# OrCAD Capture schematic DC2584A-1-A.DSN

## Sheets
1 Active Bridge: size Custom
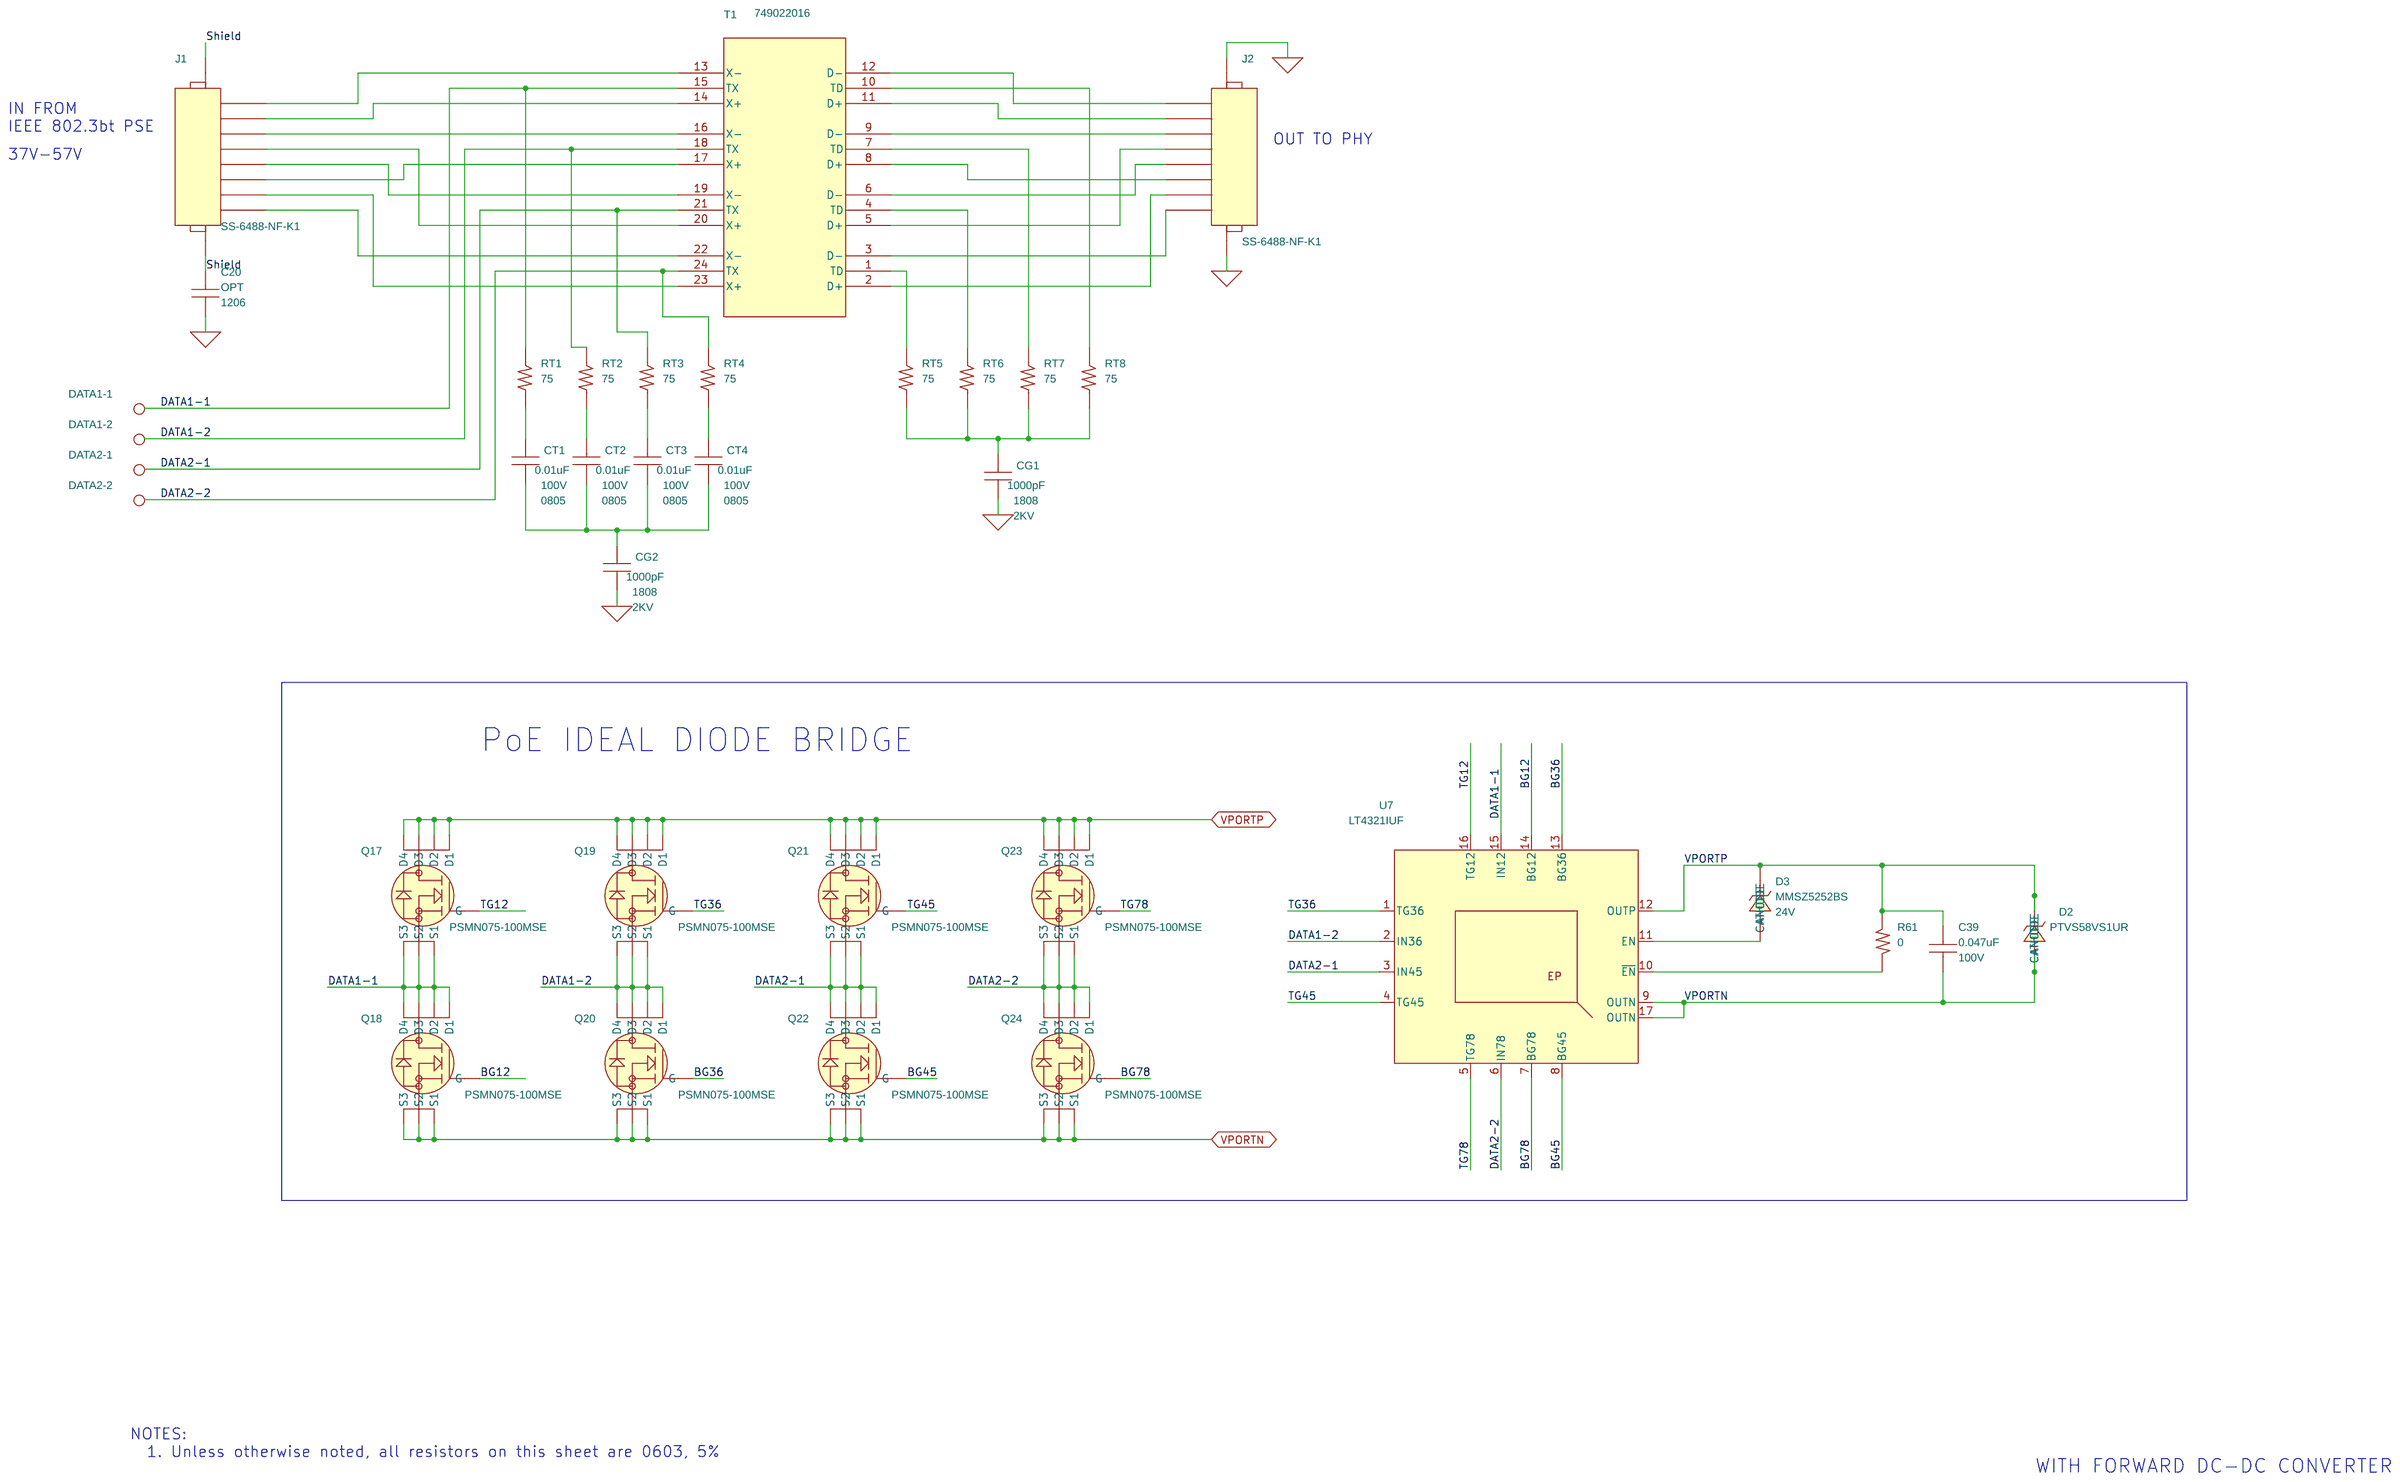
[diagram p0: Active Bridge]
2 Gate Driver Clamps: size Custom; title: IEEE 802.3bt POWERED DEVICE INTERFACE; rev: 1; company: TM
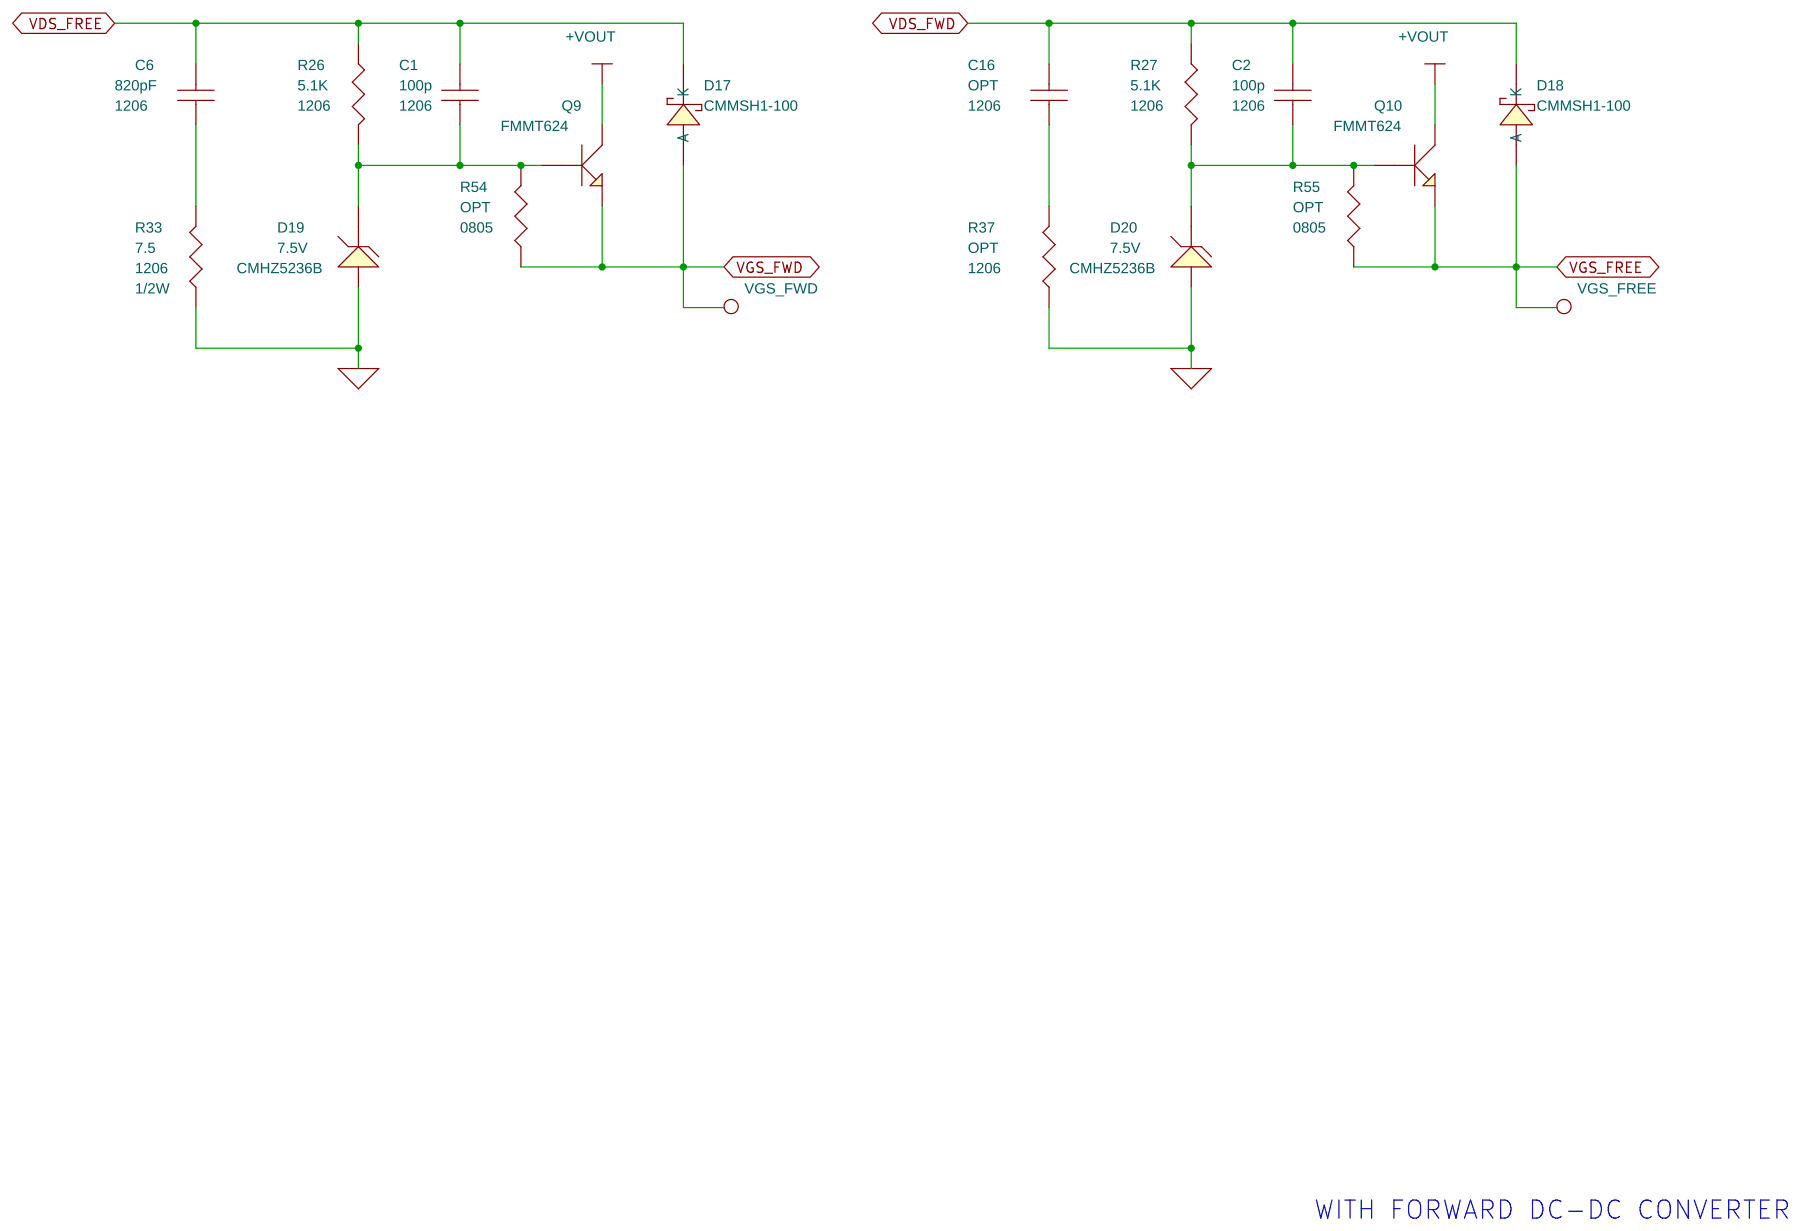
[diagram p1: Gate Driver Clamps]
3 PD + Power Supply: size Custom
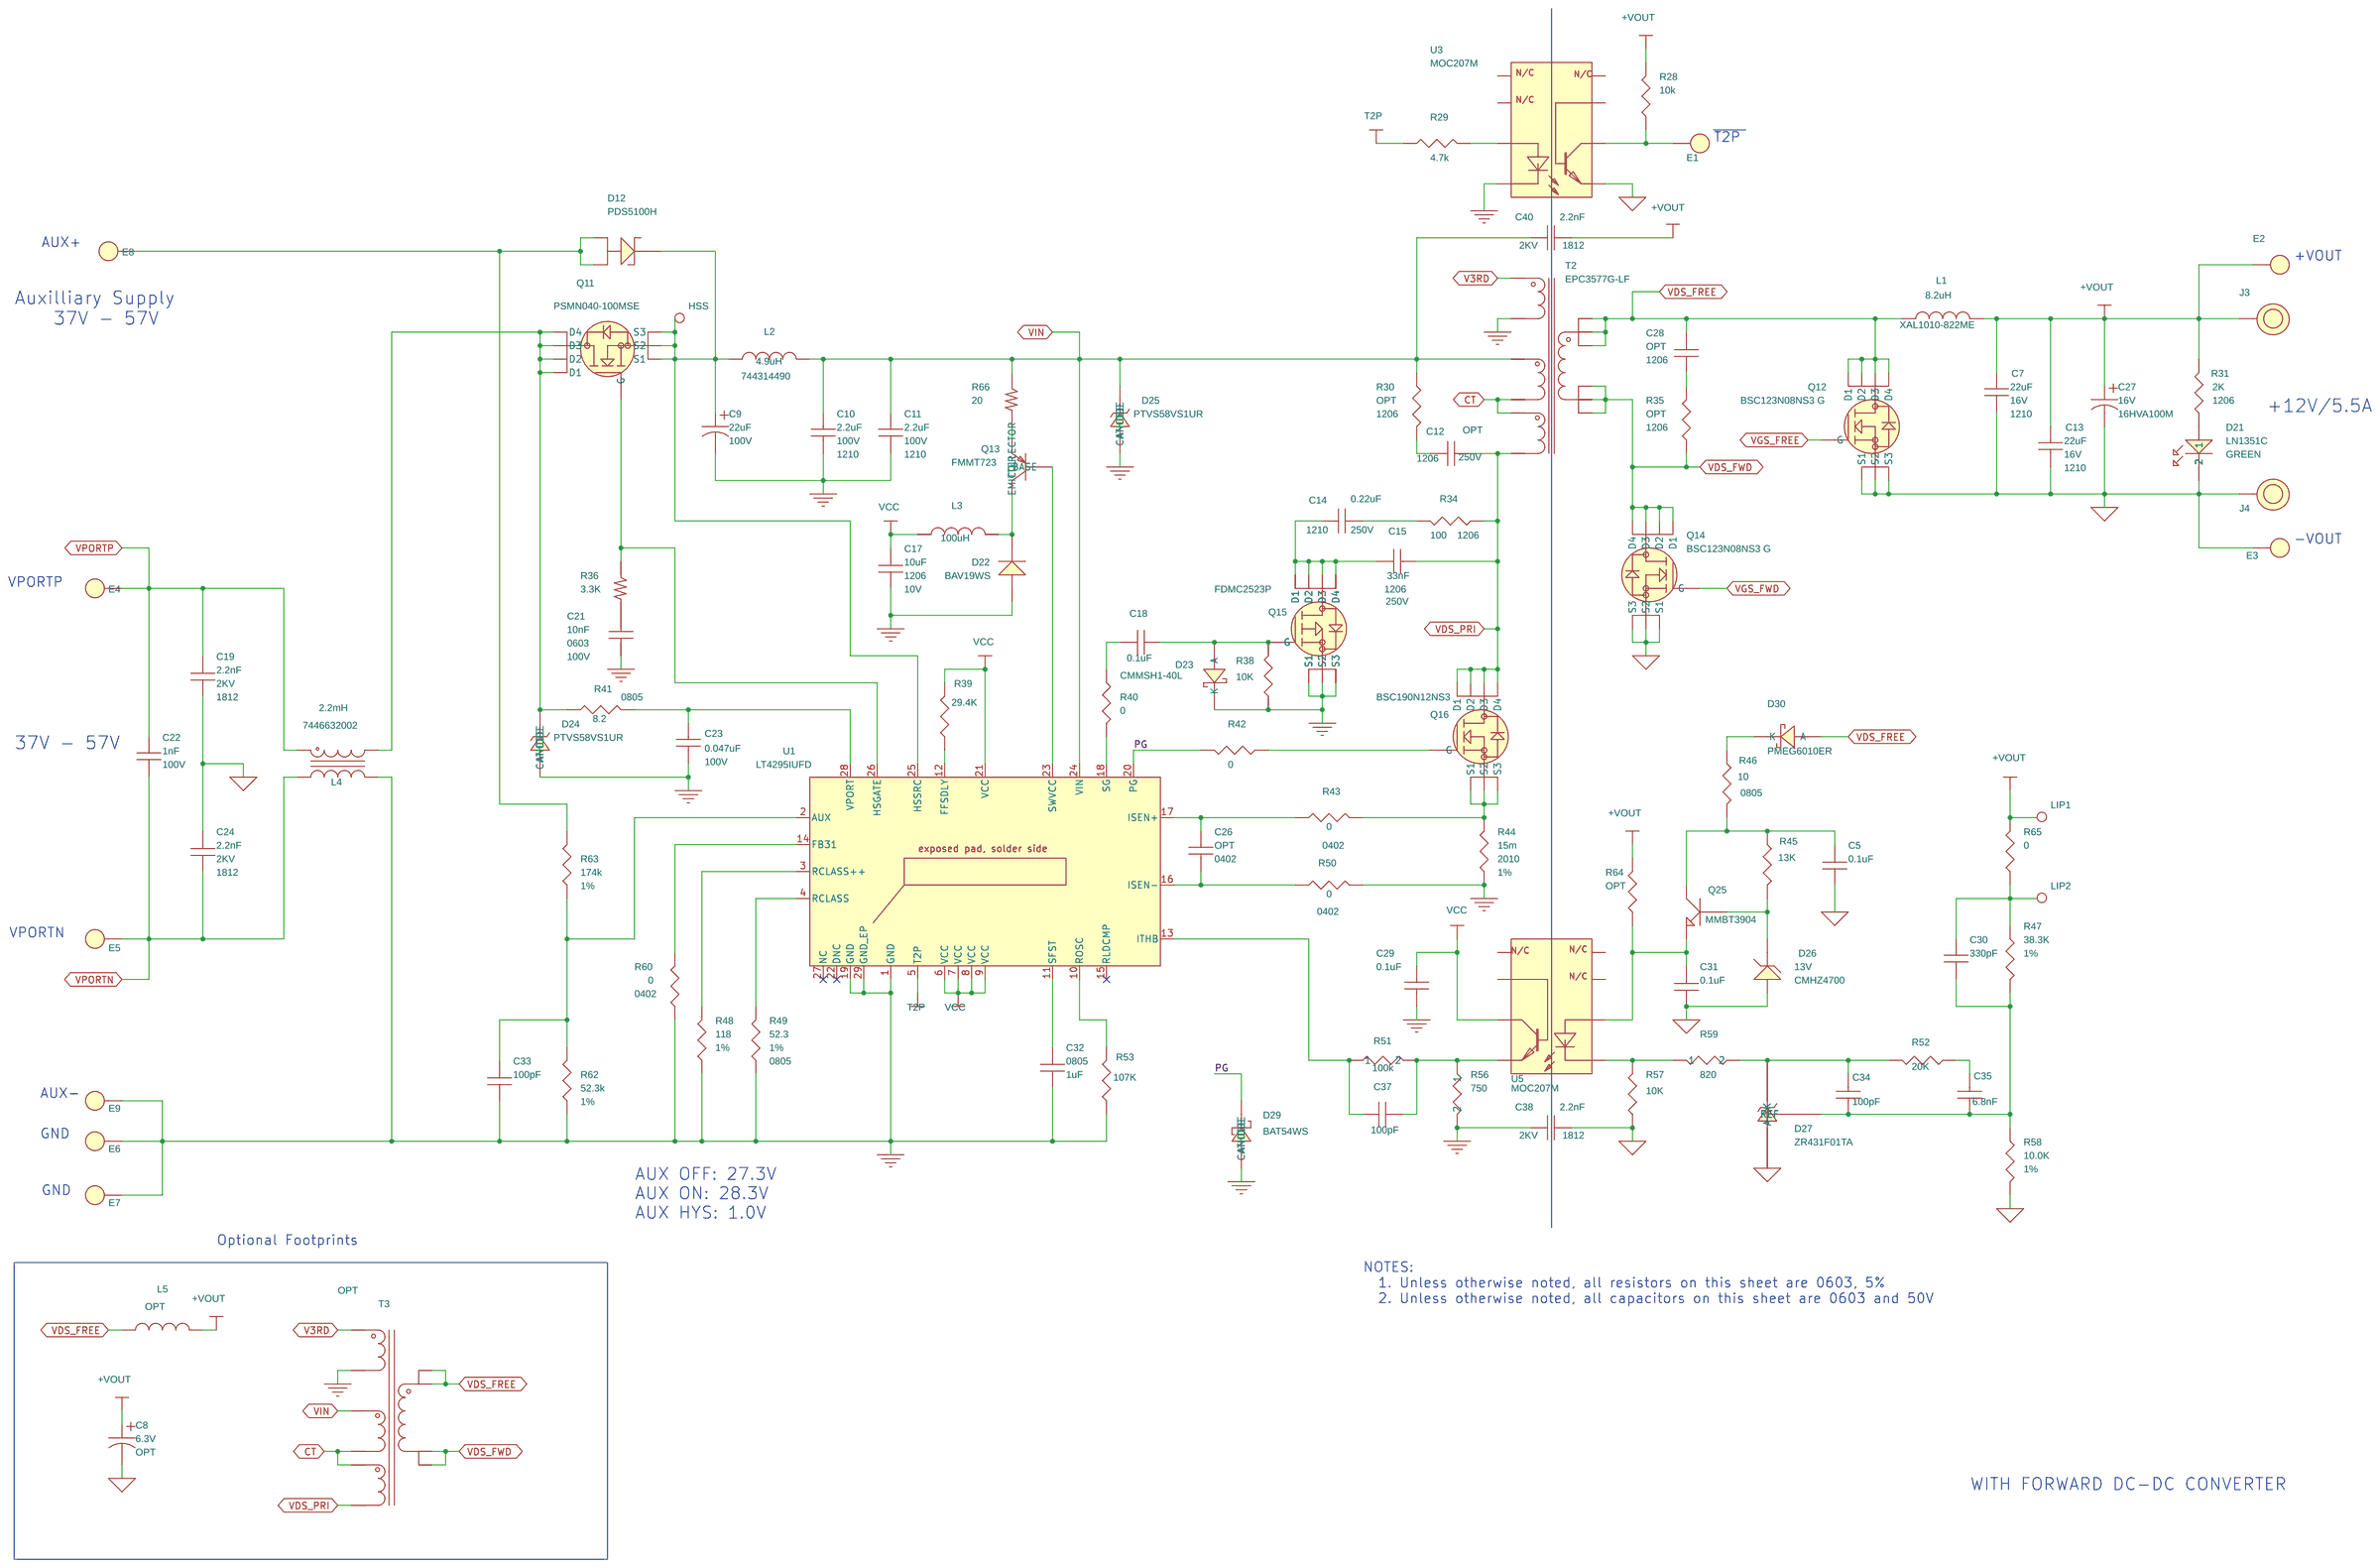
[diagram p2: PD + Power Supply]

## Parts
sheet Active Bridge
C20  OPT  [1206]
C39  0.047uF  [0603]
CG1  1000pF  [1808]
CG2  1000pF  [1808]
CT1  0.01uF  [0805]
CT2  0.01uF  [0805]
CT3  0.01uF  [0805]
CT4  0.01uF  [0805]
D2  PTVS58VS1UR  [SOD123]
D3  MMSZ5252BS  [SOD323]
DATA1-1  E-SMT-060  [SMTP]
DATA1-2  E-SMT-060  [SMTP]
DATA2-1  E-SMT-060  [SMTP]
DATA2-2  E-SMT-060  [SMTP]
J1  SS-6488-NF-K1  [CON-SS7188]
J2  SS-6488-NF-K1  [CON-SS7188]
Q17  PSMN075-100MSE  [POWERPAK1212]
Q18  PSMN075-100MSE  [POWERPAK1212]
Q19  PSMN075-100MSE  [POWERPAK1212]
Q20  PSMN075-100MSE  [POWERPAK1212]
Q21  PSMN075-100MSE  [POWERPAK1212]
Q22  PSMN075-100MSE  [POWERPAK1212]
Q23  PSMN075-100MSE  [POWERPAK1212]
Q24  PSMN075-100MSE  [POWERPAK1212]
R61  0  [0603]
RT1  75  [0603]
RT2  75  [0603]
RT3  75  [0603]
RT4  75  [0603]
RT5  75  [0603]
RT6  75  [0603]
RT7  75  [0603]
RT8  75  [0603]
T1  749022016  [749022016]
U7  LT4321IUF  [QFN16UF-4X4]
sheet Gate Driver Clamps
C1  100p  [1206]
C2  100p  [1206]
C6  820pF  [1206]
C16  OPT  [1206]
D17  CMMSH1-100  [SOD123F]
D18  CMMSH1-100  [SOD123F]
D19  CMHZ5236B  [SOD123]
D20  CMHZ5236B  [SOD123]
Q9  FMMT624  [SOT23]
Q10  FMMT624  [SOT23]
R26  5.1K  [1206]
R27  5.1K  [1206]
R33  7.5  [1206]
R37  OPT  [1206]
R54  OPT  [0805]
R55  OPT  [0805]
VGS_FREE  E-SMT-060  [SMTP]
VGS_FWD  E-SMT-060  [SMTP]
sheet PD + Power Supply
C5  0.1uF  [0603]
C7  22uF  [1210]
C8  OPT  [C-SANYO-CV-FS-6.3X6.0]
C9  22uF  [C-SANYO-CE-BS-8X10.2]
C10  2.2uF  [1210]
C11  2.2uF  [1210]
C12  OPT  [1206]
C13  22uF  [1210]
C14  0.22uF  [1206]
C15  33nF  [1206]
C17  10uF  [1206]
C18  0.1uF  [0603]
C19  2.2nF  [1812]
C21  10nF  [0603]
C22  1nF  [0603]
C23  0.047uF  [0603]
C24  2.2nF  [1812]
C26  OPT  [0402]
C27  100uF  [C-SANYO-HVH-8x10.5]
C28  OPT  [1206]
C29  0.1uF  [0603]
C30  330pF  [0603]
C31  0.1uF  [0603]
C32  1uF  [0805]
C33  100pF  [0603]
C34  100pF  [0603]
C35  6.8nF  [0603]
C37  100pF  [0603]
C38  2.2nF  [1812]
C40  2.2nF  [1812]
D12  PDS5100H  [POWER-DI-5]
D21  LN1351C  [LED-LN1351C-GREEN]
D22  BAV19WS  [SOD323]
D23  CMMSH1-40L  [SOD123F]
D24  PTVS58VS1UR  [SOD123]
D25  PTVS58VS1UR  [SOD123]
D26  CMHZ4700  [SOD123]
D27  ZR431F01TA  [SOT23]
D29  BAT54WS  [SOD323]
D30  PMEG6010ER  [SOD123F]
E1  PAD150-094  [PAD150-094]
E2  PAD150-094  [PAD150-094]
E3  PAD150-094  [PAD150-094]
E4  PAD150-094  [PAD150-094]
E5  PAD150-094  [PAD150-094]
E6  PAD150-094  [PAD150-094]
E7  PAD150-094  [PAD150-094]
E8  PAD150-094  [PAD150-094]
E9  PAD150-094  [PAD150-094]
HSS  E-SMT-060  [SMTP]
J3  575-4  [KEY-575-4]
J4  575-4  [KEY-575-4]
L1  8.2uH  [IND-COILCRAFT-XAL1010-102]
L2  4.9uH  [IND-744314490]
L3  100uH  [IND-DT1608C]
L4  2.2mH  [IND-7446632002]
L5  OPT  [IND-HC1]
LIP1  E-SMT-060  [SMTP]
LIP2  E-SMT-060  [SMTP]
Q11  PSMN040-100MSE  [POWER33]
Q12  BSC123N08NS3 G  [SO8-POWERPAK-BIG-NS]
Q13  FMMT723  [SOT23]
Q14  BSC123N08NS3 G  [SO8-POWERPAK-BIG-NS]
Q15  FDMC2523P  [POWER33]
Q16  BSC190N12NS3  [SO8-POWERPAK-BIG-NS]
Q25  MMBT3904  [SOT23]
R28  10k  [0603]
R29  4.7k  [0603]
R30  OPT  [1206]
R31  2K  [1206]
R34  100  [1206]
R35  OPT  [1206]
R36  3.3K  [0603]
R38  10K  [0603]
R39  29.4K  [0603]
R40  0  [0603]
R41  8.2  [0805]
R42  0  [0603]
R43  0  [0402]
R44  15m  [2010]
R45  13K  [0603]
R46  10  [0805]
R47  38.3K  [0603]
R48  118  [0603]
R49  52.3  [0805]
R50  0  [0402]
R51  100k  [0603]
R52  20K  [0603]
R53  107K  [0603]
R56  750  [0603]
R57  10K  [0603]
R58  10.0K  [0603]
R59  820  [0603]
R60  0  [0402]
R62  52.3k  [0603]
R63  174k  [0603]
R64  OPT  [0603]
R65  0  [0603]
R66  20  [0805]
T2  EPC3577G-LF  [TRANS-PB2134]
T3  OPT  [TRANS-PH08XXCNL]
U1  LT4295IUFD  [QFN28UFD-4X5]
U3  MOC207M  [SO8NB]
U5  MOC207M  [SO8NB]

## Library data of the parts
C12 C20 = CAP-NP: 1st Part: CAP; 2nd Part Type: CER; 3rd Tempco: X7R; 5th Voltage: 250V; 6th Tolerance: 10%; 8th Mfr: TBD; 9th Part Number: TBD
C39 = CAP-NP: 1st Part: CAP; 2nd Part Type: Cer; 3rd Tempco: X7R; 5th Voltage: 100V; 6th Tolerance: 20%; 8th Mfr: TBD; Voltage Rating: 100V
CG1 CG2 = CAP-NP: 1st Part: CAP; 2nd Part Type: CER; 3rd Tempco: X7R; 5th Voltage: 2KV; 6th Tolerance: ??%; 8th Mfr: TBD; 9th Part Number: TBD; Voltage Rating: 2KV
CT1-CT4 = CAP-NP: 1st Part: CAP; 2nd Part Type: CER; 3rd Tempco: X7R; 5th Voltage: 100V; 6th Tolerance: 20%; 8th Mfr: TBD; 9th Part Number: TBD; Voltage Rating: 100V
D2 = DIODE_ZENER_0: 1st Part: DIODE; 2nd Part Type: TVS; 5th Voltage: 60; 8th Mfr: NXP
D3 = DIODE_ZENER_0: 1st Part: DIODE; 2nd Part Type: Zener; 5th Voltage: 24V; 8th Mfr: Diodes Inc
DATA1-1 DATA1-2 DATA2-1 DATA2-2 HSS LIP1 LIP2 VGS_FREE VGS_FWD = E-SMT-060: 1st Part: CONN; 2nd Part Type: TP
J1 J2 = 8_HEADER_1: 1st Part: CONN; 2nd Part Type: RJ-45; 8th Mfr: STEWART CONNECTOR
Q17-Q24 = MOSFET_N-DIODE-A-SO8: 1st Part: MOSFET; 2nd Part Type: N-CH; 5th Voltage: 100; 7th Size: LFPAK33; 8th Mfr: NXP
R61 = R: 1st Part: Res; 2nd Part Type: Chip; 6th Tolerance: 5%; 8th Mfr: TBD; Tolerance: 5%
RT1-RT8 = R: 1st Part: Res; 2nd Part Type: Chip; 6th Tolerance: 5%; 8th Mfr: TBD; 9th Part Number: TBD; Tolerance: 5%
T1 = 749022016MOD: 1st Part: TRANSFORMER; 2nd Part Type: ETHERNET; 8th Mfr: WURTH; Optional: *
U7 = LT4321_QFN_1: 1st Part: IC; 2nd Part Type: PoE Ideal Bridge Controller; 7th Size: QFN16; 8th Mfr: Linear Tech; 9th Part Number: LT4321
C1 C2 C6 C16 = CAP-NP: 1st Part: CAP; 2nd Part Type: CER; 3rd Tempco: X7R; 5th Voltage: 50V; 8th Mfr: TBD; 9th Part Number: TBD
D17 D18 = B0530W_0: 1st Part: DIODE; 2nd Part Type: SCHOTTKY; 5th Voltage: 100V; 7th Size: SOD-123F; 8th Mfr: CENTRAL SEMI.
D19 D20 = DIODE_ZENER1_0: 1st Part: DIODE; 2nd Part Type: ZENER; 5th Voltage: 7.5V; 7th Size: SOD-123; 8th Mfr: CENTRAL SEMI.
Q9 Q10 = NPN_8: 1st Part: TRANSISTOR; 2nd Part Type: NPN; 5th Voltage: 50V; 8th Mfr: DIODES INC.
R26 R27 R29 R40 R42 R45 R46 R64 R65 = CR18-274JM: 1st Part: Res; 2nd Part Type: Chip; 6th Tolerance: 5%; 8th Mfr: TBD; 9th Part Number: TBD
R33 R37 = CR18-274JM: 10th Power Rating: 1/2W; 1st Part: RES; 2nd Part Type: CHIP; 6th Tolerance: 5%; 8th Mfr: TBD; 9th Part Number: TBD
R39 R48 R49 R53-R55 = CR18-274JM: 1st Part: RES; 2nd Part Type: CHIP; 6th Tolerance: 1%; 8th Mfr: TBD; 9th Part Number: TBD
C5 C33 C37 = CAP-NP: 1st Part: CAP; 2nd Part Type: CER; 3rd Tempco: X7R; 5th Voltage: 50V; 6th Tolerance: 10%; 8th Mfr: TBD; 9th Part Number: TBD
C7 C13 = CAP-NP: 1st Part: CAP; 2nd Part Type: CER; 3rd Tempco: X5R; 5th Voltage: 16V; 6th Tolerance: 20%; 8th Mfr: MURATA; 9th Part Number: GRM32ER61C226ME20
C8 = CAP: 2nd Part Type: ELEC; 5th Voltage: 6.3V; 6th Tolerance: 20%; 7th Size: 6.3 X 6.0; 8th Mfr: SUNCON
C9 = CAP: 2nd Part Type: ELEC; 5th Voltage: 100V; 6th Tolerance: 20%; 7th Size: 8 X 10.2; 8th Mfr: SUNCON; 9th Part Number: 100CE22KX
C10 C11 = CAP-NP: 1st Part: CAP; 2nd Part Type: CER; 3rd Tempco: X7R; 5th Voltage: 100V; 6th Tolerance: 10%; 8th Mfr: MURATA; 9th Part Number: GRM32ER72A225KA35
C14 = CAP-NP: 1st Part: CAP; 2nd Part Type: CER; 3rd Tempco: X7R; 5th Voltage: 250V; 6th Tolerance: 10%; 7th Size: 1210; 8th Mfr: MURATA; 9th Part Number: GRM32DR72E224KW01
C15 = CAP-NP: 1st Part: CAP; 2nd Part Type: CER; 3rd Tempco: X5R; 5th Voltage: 250V; 8th Mfr: MURATA; 9th Part Number: GRM31CR72E333KW03
C17 = CAP-NP: 1st Part: CAP; 2nd Part Type: CER; 3rd Tempco: X7R; 5th Voltage: 10V; 6th Tolerance: 10%; 8th Mfr: MURATA; 9th Part Number: GRM31CR71A106KA01L
C18 C29 = CAP-NP: 1st Part: CAP; 2nd Part Type: CER; 3rd Tempco: X7R; 5th Voltage: 50V; 6th Tolerance: 20%; 8th Mfr: MURATA; 9th Part Number: GRM188R71H104MA93
C19 C24 C38 C40 = CAP-NP: 1st Part: CAP; 2nd Part Type: CER; 3rd Tempco: X7R; 5th Voltage: 2KV; 8th Mfr: MURATA; 9th Part Number: GR443QR73D222KW01L
C21 = CAP-NP: 1st Part: CAP; 2nd Part Type: CER; 3rd Tempco: X7R; 5th Voltage: 100V; 6th Tolerance: 10%; 9th Part Number: TBD
C22 = CAP-NP: 1st Part: CAP; 2nd Part Type: CER; 3rd Tempco: X7R; 5th Voltage: 100V; 6th Tolerance: 10%; 8th Mfr: MURATA; 9th Part Number: GRM188R72A102KA01
C23 = CAP-NP: 1st Part: CAP; 2nd Part Type: CER; 3rd Tempco: X7R; 5th Voltage: 100V; 6th Tolerance: 10%; 8th Mfr: TBD; 9th Part Number: TBD
C26 = CAP-NP: 1st Part: CAP; 2nd Part Type: CER; 3rd Tempco: X7R; 5th Voltage: 50V; 6th Tolerance: 20%; 8th Mfr: TBD; 9th Part Number: TBD
C27 = CAP: 2nd Part Type: ELEC; 5th Voltage: 16V; 6th Tolerance: 20%; 7th Size: 8 X 10.5; 8th Mfr: SUNCON; 9th Part Number: 16HVA100M
C28 = CAP-NP: 1st Part: CAP; 2nd Part Type: CER; 3rd Tempco: X7R; 5th Voltage: 100V; 8th Mfr: TBD; 9th Part Number: TBD
C30 = CAP-NP: 1st Part: CAP; 2nd Part Type: CER; 3rd Tempco: X7R; 5th Voltage: 50V; 6th Tolerance: 10%; 8th Mfr: TBD; 9th Part Number: TBD; Part Number: AVX 06033A681KAT2A
C31 = EMK212BJ105MG: 1st Part: CAP; 2nd Part Type: CER; 3rd Tempco: X7R; 5th Voltage: 50V; 6th Tolerance: 10%; 8th Mfr: TBD; 9th Part Number: TBD
C32 = CAP-NP: 1st Part: CAP; 2nd Part Type: CER; 3rd Tempco: X7R; 5th Voltage: 10V; 6th Tolerance: 10%; 8th Mfr: TBD; 9th Part Number: TBD
C34 = 12063A222KAT2A: 1st Part: CAP; 2nd Part Type: CER; 3rd Tempco: X7R; 5th Voltage: 50V; 6th Tolerance: 10%; 8th Mfr: TBD; 9th Part Number: TBD
C35 = 12063A222KAT2A_1: 1st Part: CAP; 2nd Part Type: CER; 3rd Tempco: X7R; 5th Voltage: 50V; 6th Tolerance: 10%; 8th Mfr: TBD; 9th Part Number: TBD
D12 = DIODE_ZENER_6: DIODE, TRANSIENT VOLTAGE SUPRESSOR 400W; 1st Part: DIODE; 2nd Part Type: SCHOTTKY; 5th Voltage: 100V; 7th Size: PowerDI5; 8th Mfr: DIODES INC; Part Number: DIODES INC. SMAJ58A
D21 = LED_0: 1st Part: DIODE; 2nd Part Type: LED; 5th Voltage: GREEN; 8th Mfr: PANASONIC; GREEN: GREEN
D22 = DIODE_0: 1st Part: DIODE; 2nd Part Type: SILICON; 5th Voltage: 120V; 7th Size: SOD-323; 8th Mfr: DIODES INC.
D23 = B0530W_0: 1st Part: DIODE; 2nd Part Type: SCHOTTKY; 5th Voltage: 40V; 7th Size: SOD-123F; 8th Mfr: CENTRAL SEMI.
D24 D25 = DIODE_ZENER_0: 1st Part: DIODE; 2nd Part Type: TVS; 5th Voltage: 58V; 8th Mfr: NXP
D26 = DIODE_ZENER1_0: 1st Part: DIODE; 2nd Part Type: ZENER; 5th Voltage: 13V; 7th Size: SOD-123; 8th Mfr: CENTRAL SEMI.
D27 = LM431_SOT_1: REGULATOR, LOW VOLTAGE; 1st Part: IC; 2nd Part Type: REFERENCE; 8th Mfr: DIODES INC; Part Number: ZETEX ZR431F01
D29 = DIODE_SCHOTTKY_0: 1st Part: Diode; 2nd Part Type: Schottky; 5th Voltage: 30V; 8th Mfr: DIODE INC
D30 = B0530W_0: 1st Part: DIODE; 2nd Part Type: SCHOTTKY; 5th Voltage: 60V; 7th Size: SOD-123F; 8th Mfr: NXP
E1-E3 = E: 1st Part: TP; 2nd Part Type: TURRET; 7th Size: 0.094"; 8th Mfr: MILL-MAX; 9th Part Number: 2501-2-00-80-00-00-07-0
E4-E9 = E: TURRETS; 1st Part: TP; 2nd Part Type: TURRET; 7th Size: 0.094"; 8th Mfr: MILL-MAX; 9th Part Number: 2501-2-00-80-00-00-07-0; Part Number: MILLMAX 2501-2
J3 J4 = KEY-575--4_0: 1st Part: CONN; 2nd Part Type: BANANA; 7th Size: 0.175"; 8th Mfr: KEYSTONE
L1 = IND: 7th Size: XAL1010; 8th Mfr: COILCRAFT; 9th Part Number: XAL1010-822ME
L2 = IND: 8th Mfr: WURTH; 9th Part Number: 744314490
L3 = IND: 7th Size: DO1608; 8th Mfr: COILCRAFT; 9th Part Number: DO1608C-104
L4 = IND_0: 1st Part: IND; 2nd Part Type: CMC; 7th Size: WE-LF; 8th Mfr: WURTH; 9th Part Number: 7446632002
L5 = IND: 4th Value: 0.87uH; 7th Size: HC1; 8th Mfr: COILTRONICS; 9th Part Number: HC1-R87
Q11 = MOSFET_N-DIODE-A-SO8: 1st Part: MOSFET; 2nd Part Type: N-CH; 5th Voltage: 100V; 7th Size: POWER 33; 8th Mfr: NXP
Q12 Q14 = MOSFET_N-DIODE-A-SO8: 1st Part: MOSFET; 2nd Part Type: N-CH; 5th Voltage: 80V; 7th Size: POWER56; 8th Mfr: FAIRCHILD
Q13 = 2N5401_0: 1st Part: TRANSISTOR; 2nd Part Type: PNP; 5th Voltage: 100V; 8th Mfr: DIODES INC.; Part Number: DIODES INC. MMBT5401
Q15 = MOSFET_N-DIODE-A-SO8_0: 1st Part: MOSFET; 2nd Part Type: N-CH; 5th Voltage: 150V; 7th Size: POWER 33; 8th Mfr: FAIRCHILD
Q16 = MOSFET_N-DIODE-A-SO8: 1st Part: MOSFET; 2nd Part Type: N-CH; 5th Voltage: 120V; 7th Size: PG-TDSON-8; 8th Mfr: INFINEON
Q25 = NPN_8: 1st Part: TRANSISTOR; 2nd Part Type: NPN; 5th Voltage: 40V; 8th Mfr: DIODES INC.; 9th Part Number: OPT
R28 R30 R31 R34 R35 R38 R41 R43 R50 R60 = CR18-274JM: 1st Part: RES; 2nd Part Type: CHIP; 6th Tolerance: 5%; 8th Mfr: TBD; 9th Part Number: TBD
R36 R66 = R: 1st Part: RES; 2nd Part Type: CHIP; 6th Tolerance: 5%; 8th Mfr: TBD; 9th Part Number: TBD
R44 = CR18-274JM: 1st Part: RES; 2nd Part Type: CHIP; 6th Tolerance: 1%; 8th Mfr: VISHAY; 9th Part Number: WSL2010R0150FEA / WSL2010R0150FEA
R47 R58 = CR10-1242FM: 1st Part: RES; 2nd Part Type: CHIP; 6th Tolerance: 1%; 8th Mfr: TBD; 9th Part Number: TBD
R51 = CR10-103JM: 1st Part: RES; 2nd Part Type: CHIP; 6th Tolerance: 5%; 8th Mfr: TBD; 9th Part Number: TBD
R52 = CR10-1242FM: 1st Part: RES; 2nd Part Type: CHIP; 6th Tolerance: 5%; 8th Mfr: TBD; 9th Part Number: TBD
R56 = CR10-103JM_2: 1st Part: RES; 2nd Part Type: CHIP; 6th Tolerance: 5%; 8th Mfr: TBD; 9th Part Number: TBD
R57 = CR10-821JM: 1st Part: RES; 2nd Part Type: CHIP; 6th Tolerance: 5%; 8th Mfr: TBD; 9th Part Number: TBD
R59 = CR10-103JM_1: 1st Part: Res; 2nd Part Type: Chip; 6th Tolerance: 5%; 8th Mfr: TBD; 9th Part Number: TBD
R62 R63 = CR18-274JM: 1st Part: Res; 2nd Part Type: Chip; 6th Tolerance: 1%; 8th Mfr: TBD; 9th Part Number: TBD
T2 = TRANS-VP3_8: 1st Part: TRANSFORMER; 2nd Part Type: FORWARD; 7th Size: EFD20; 8th Mfr: PCA
T3 = TRANS-VP3_7: 1st Part: TRANSFORMER; 2nd Part Type: FORWARD; 7th Size: EFD20; 8th Mfr: PULSE; 9th Part Number: PA0814.006
U1 = LT4276_5: 1st Part: IC; 2nd Part Type: PD & Switcher Controller; 7th Size: QFN28; 8th Mfr: Linear Tech
U3 U5 = HCPL-M453_0: 1st Part: OPTO; 7th Size: SOIC-8; 8th Mfr: FAIRCHILD

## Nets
GND_POWER: C9.2 C10.2 C11.2 C17.1 C21.2 C23.2 C29.2 C32.1 C33.1 C38.1 D22.2 D23.1(K) D24.2(ANODE) D25.2(ANODE) D29.2(ANODE) E6.1(A) E7.1(A) E9.1(A) L4.2 Q15.1(S1) Q15.2(S2) Q15.3(S3) R38.1 R44.2 R48.1 R49.1 R50.2 R53.1 R56.2 R60.1 R62.1 T2.6 T3.6 U1.1(GND) U1.19(GND) U1.29(GND_EP) U3.2
V3RD: T2.1 T3.1
VCC: C17.2 C29.1 L3.1 R39.2 U1.6(VCC) U1.7(VCC) U1.8(VCC) U1.9(VCC) U1.21(VCC) U5.6
VIN: C10.1 C11.1 C40.1 D25.1(CATHODE) L2.2 R30.2 R66.1 T2.2 T3.2 U1.24(VIN)
+VOUT: C7.1 C8.1 C13.1 C27.1 C40.2 E2.1(A) J3.1 L1.2 L5.2 LIP1.1 Q9.3(COLLECTOR) Q10.3(COLLECTOR) R28.2 R31.2 R64.2 R65.2
BG12: Q18.4(G) U7.14(BG12)
BG36: Q20.4(G) U7.13(BG36)
BG45: Q22.4(G) U7.8(BG45)
BG78: Q24.4(G) U7.7(BG78)
CT: T2.3 T2.4 T3.3 T3.4
DATA1-1: DATA1-1.1 Q17.1(S1) Q17.2(S2) Q17.3(S3) Q18.5(D1) Q18.6(D2) Q18.7(D3) Q18.8(D4) RT1.1 T1.15(TX) U7.15(IN12)
DATA1-2: DATA1-2.1 Q19.1(S1) Q19.2(S2) Q19.3(S3) Q20.5(D1) Q20.6(D2) Q20.7(D3) Q20.8(D4) RT2.1 T1.18(TX) U7.2(IN36)
DATA2-1: DATA2-1.1 Q21.1(S1) Q21.2(S2) Q21.3(S3) Q22.5(D1) Q22.6(D2) Q22.7(D3) Q22.8(D4) RT3.1 T1.21(TX) U7.3(IN45)
DATA2-2: DATA2-2.1 Q23.1(S1) Q23.2(S2) Q23.3(S3) Q24.5(D1) Q24.6(D2) Q24.7(D3) Q24.8(D4) RT4.1 T1.24(TX) U7.6(IN78)
PG: D29.1(CATHODE) R42.2 U1.20(PG)
SEC_GND: C5.1 C7.2 C8.2 C13.2 C19.1 C20.2 C24.2 C27.2 C31.1 C38.2 CG1.2 CG2.2 D19.2 D20.2 D21.2 D26.2 D27.3(A) E3.1(A) J2.9 J2.10 J4.1 Q12.1(S1) Q12.2(S2) Q12.3(S3) Q14.1(S1) Q14.2(S2) Q14.3(S3) R33.1 R37.1 R57.1 R58.2 U3.5
Shield: C20.1 J1.9 J1.10
T2P: R29.1 U1.5(T2P)
TG12: Q17.4(G) U7.16(TG12)
TG36: Q19.4(G) U7.1(TG36)
TG45: Q21.4(G) U7.4(TG45)
TG78: Q23.4(G) U7.5(TG78)
VDS_FREE: C1.2 C6.2 C28.2 D17.1(K) D30.2(A) L1.1 L5.1 Q12.5(D1) Q12.6(D2) Q12.7(D3) Q12.8(D4) R26.2 T2.7 T2.8 T2.9 T3.7 T3.8
VDS_FWD: C2.2 C16.2 D18.1(K) Q14.5(D1) Q14.6(D2) Q14.7(D3) Q14.8(D4) R27.2 R35.1 T2.10 T2.11 T2.12 T3.10 T3.11
VDS_PRI: C12.1 C15.1 Q16.5(D1) Q16.6(D2) Q16.7(D3) Q16.8(D4) R34.1 T2.5 T3.5
VGS_FREE: D18.2(A) Q10.2 Q12.4(G) R55.1 VGS_FREE.1
VGS_FWD: D17.2(A) Q9.2 Q14.4(G) R54.1 VGS_FWD.1
VPORTN: C22.2 C24.1 C39.2 D2.2(ANODE) E5.1(A) L4.1 Q18.1(S1) Q18.2(S2) Q18.3(S3) Q20.1(S1) Q20.2(S2) Q20.3(S3) Q22.1(S1) Q22.2(S2) Q22.3(S3) Q24.1(S1) Q24.2(S2) Q24.3(S3) U7.9(OUTN) U7.17(OUTN)
VPORTP: C19.2 C22.1 C39.1 D2.1(CATHODE) D3.1(CATHODE) E4.1(A) L4.4 Q17.5(D1) Q17.6(D2) Q17.7(D3) Q17.8(D4) Q19.5(D1) Q19.6(D2) Q19.7(D3) Q19.8(D4) Q21.5(D1) Q21.6(D2) Q21.7(D3) Q21.8(D4) Q23.5(D1) Q23.6(D2) Q23.7(D3) Q23.8(D4) R61.1 U7.12(OUTP)
N16777767: D24.1(CATHODE) L4.3 Q11.5(D1) Q11.6(D2) Q11.7(D3) Q11.8(D4) R41.1
N16778156: C9.1 D12.1 HSS.1 L2.1 Q11.1(S1) Q11.2(S2) Q11.3(S3) U1.25(HSSRC)
N16853335: Q11.4(G) R36.1 U1.26(HSGATE)
N16869121: C23.1 R41.2 U1.28(VPORT)
N16912256: R53.2 U1.10(ROSC)
N16989975: Q16.1(S1) Q16.2(S2) Q16.3(S3) R43.2 R44.1
N17470232: C26.1 R43.1 U1.17(ISEN+)
N17471634: C26.2 R50.1 U1.16(ISEN-)
N17491181: Q13.1(BASE) U1.23(SWVCC)
N17578166: CG1.1 RT5.2 RT6.2 RT7.2 RT8.2
N17578282: CT1.1 RT1.2
N17578284: J2.5 T1.6(D-)
N17578286: J2.8 T1.3(D-)
N17578288: J2.4 T1.5(D+)
N17578290: J2.7 T1.2(D+)
N17578292: CT2.1 RT2.2
N17578294: CT3.1 RT3.2
N17578302: CT4.1 RT4.2
N17578307: CG2.1 CT1.2 CT2.2 CT3.2 CT4.2
N17578317: J1.2 T1.14(X+)
N17578321: RT5.1 T1.1(TD)
N17578333: RT6.1 T1.4(TD)
N17578343: RT7.1 T1.7(TD)
N17578347: RT8.1 T1.10(TD)
N17578441: J1.1 T1.13(X-)
N17578443: J1.3 T1.16(X-)
N17578447: J1.6 T1.17(X+)
N17578449: J1.5 T1.19(X-)
N17578451: J1.4 T1.20(X+)
N17578453: J1.8 T1.22(X-)
N17578455: J2.1 T1.12(D-)
N17578459: J1.7 T1.23(X+)
N17578461: J2.6 T1.8(D+)
N17578463: J2.3 T1.9(D-)
N17578465: J2.2 T1.11(D+)
N17720354: C18.1 D23.2(A) Q15.4(G) R38.2
N17736851: C14.1 C15.2 Q15.5(D1) Q15.6(D2) Q15.7(D3) Q15.8(D4)
N17769247: C14.2 R34.2
N17776032: C12.2 R30.1
N17859202: C1.1 D19.1 Q9.1 R26.1 R54.2
N17898128: C2.1 D20.1 Q10.1 R27.1 R55.2
N17967906: D22.1 L3.2 Q13.3(COLLECTOR)
N18012236: R49.2 U1.4(RCLASS)
N18015217: R48.2 U1.3(RCLASS++)
N18230147: C18.2 R40.1
N18580909: C37.2 R51.2 R56.1 U5.5
N18582872: E1.1(A) R28.1 U3.6
N18582891: R29.2 U3.1
N18585755: C30.1 LIP2.1 R47.1 R65.1
N18621423: C30.2 C34.1 C35.1 D27.1(REF) R47.2 R58.1
N18663045: C35.2 R52.2
N18723580: C37.1 R51.1 U1.13(ITHB)
N18787052: C31.2 Q25.2 R64.1 U5.1
N18823954: R57.2 R59.1 U5.2
N18984920: R60.2 U1.14(FB31)
N19384409: D3.2(ANODE) U7.11(EN)
N19384432: R61.2 U7.10(~{EN})
N19428436: R39.1 U1.12(FFSDLY)
N19433326: C32.2 U1.11(SFST)
N19490275: C34.2 D27.2(K) R52.1 R59.2
N19519743: C5.2 Q25.3(COLLECTOR) R45.2 R46.1
N19520227: D26.1 Q25.1 R45.1
N19527484: D30.1(K) R46.2
N19560796: C6.1 R33.2
N19597976: C16.1 R37.2
N19637840: C28.1 R35.2
N19648855: C33.2 R62.2 R63.1 U1.2(AUX)
N19652390: D12.2 D12.3 E8.1(A) R63.2
N19802595: Q13.2(EMITTER) R66.2
N19916023: Q16.4(G) R42.1
N19921421: R40.2 U1.18(SG)
N20053475: C21.1 R36.2
N20053476: D21.1 R31.1

Not connected (* = marked no-connect by the designer): U1 15(RLDCMP)* 22(DNC)* 27(NC)*; U3 3 4 7 8; U5 3 4 7 8

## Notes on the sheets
sheet 1
- IN FROM
  IEEE 802.3bt PSE
- OUT TO PHY
- 37V-57V
- PoE IDEAL DIODE BRIDGE
- NOTES:
    1. Unless otherwise noted, all resistors on this sheet are 0603, 5%
- WITH FORWARD DC-DC CONVERTER
sheet 2
- WITH FORWARD DC-DC CONVERTER
sheet 3
- T2P
- AUX+
- +VOUT
- Auxilliary Supply
      37V - 57V
- +12V/5.5A
- -VOUT
- VPORTP
- 37V - 57V
- VPORTN
- AUX-
- GND
- AUX OFF: 27.3V
  AUX ON: 28.3V
  AUX HYS: 1.0V
- GND
- Optional Footprints
- NOTES:
    1. Unless otherwise noted, all resistors on this sheet are 0603, 5%
    2. Unless otherwise noted, all capacitors on this sheet are 0603 and 50V
- WITH FORWARD DC-DC CONVERTER
